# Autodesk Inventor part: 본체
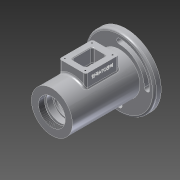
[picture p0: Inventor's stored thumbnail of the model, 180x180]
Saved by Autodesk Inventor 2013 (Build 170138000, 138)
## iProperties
Created: 2017-05
Part Number: 본체
Material: 알루미늄 6061
Document SubType Name: Modeling
Designer: MR
Density: 2.71 g/cm^3
Mass: 688.343 g
Surface Area: 623.745 cm^2
Volume: 254.001 cm^3
Author: MR
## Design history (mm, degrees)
sketch "스케치2"
  geometry: C1 r 31 at (0, 0); 1 further point
  constraints: 1 centre point, 1 coincident
  dimensions: "d0" = 62 diameter of C1
extrude "돌출1" new body sketch "스케치2" distance "d2" = 115; taper "d3" = 0 deg
sketch "스케치3"
  geometry: L1 (-31, -115)-(-31, 0) reference; L2 (-31, 0)-(31, 0) reference; L3 (31, 0)-(31, -115) reference; L4 (31, -115)-(-31, -115) reference; L5 (-31, -115)-(-31, 0) reference; L6 (-31, 0)-(31, 0) reference; L7 (31, 0)-(31, -115) reference; L8 (31, -115)-(-31, -115) reference; L9 (20, 0)-(20, -9); L10 (20, -9)-(24, -9); L11 (24, -9)-(24, -12); L12 (24, -12)-(20, -12); L13 (20, -12)-(20, -21); L14 (20, -21)-(17.5, -21); L15 (17.5, -21)-(17.5, -24.25); L16 (17.5, -24.25)-(18.5, -24.25); L17 (18.5, -24.25)-(18.5, -26); L18 (18.5, -26)-(17.5, -26); L19 (17.5, -26)-(17.5, -37); L20 (17.5, -37)-(26, -37); L21 (26, -37)-(26, -75); L22 (26, -75)-(17.5, -75); L23 (17.5, -75)-(17.5, -86); L24 (17.5, -86)-(16.5, -86); L25 (16.5, -86)-(16.5, -91); L26 (16.5, -91)-(10, -91); L27 (10, -91)-(10, -93.7); L28 (10, -93.7)-(12.5, -93.7); L29 (12.904, -101)-(16, -101); L30 (16, -101)-(19, -115); L31 (0, 0)-(0, -115); L32 (12.5, -93.7)-(12.5, -100.3); L33 (12.5, -100.3)-(12.904, -101); L34 (0, 0)-(20, 0); L35 (0, -115)-(19, -115)
  constraints: 54 end point, 11 parallel, 10 perpendicular, 4 point on line, 2 collinear, 1 midpoint
  dimensions: "d4" = 38 diameter of L30.end L31; "d6" = 32 diameter of L29.end L31; "d9" = 20 diameter of L27 L31; "d11" = 38 distance of L20.end L21.end; "d12" = 3 distance of L10.end L11.end; "d13" = 12 distance from line of L12 L9.start; "d14" = 21 vertical distance of L14.end L9.start; "d15" = 26 vertical distance of L17.end L9.start; "d16" = 11 distance of L18.end L19.end; "d17" = 35 diameter of L19 L31; "d18" = 52 diameter of L21 L31; "d19" = 33 diameter of L25 L31; "d21" = 11 distance of L22.end L23.end; "d23" = 30 deg angle of L32 L33; "d24" = 0.7 distance from line of L32.end L29; "d25" = 7.3 distance between parallel lines of L28 L29; "d26" = 2.7 distance of L26.end L27.end; "d27" = 48 diameter of L11 L31; "d28" = 40 diameter of L13 L31; "d29" = 40 diameter of L9 L31; "d31" = 35 diameter of L15 L31; "d32" = 37 diameter of L17 L31; "d33" = 1.75 distance of L16.end L17.end; "d34" = 14 distance between parallel lines of L29 L4; "d35" = 25 diameter of L32 L31
revolve "회전1" sketch "스케치3" stored, may be unused: angle "d36" = 90 deg
node "작업 평면2"
sketch "스케치5"
  geometry: L1 (0, -41.5)-(0, 41.5); L2 (41.5, 0)-(-41.5, 0); C1 r 53 at (0, 0); C2 r 37.5 at (0, 0); C3 r 31 at (0, 0) reference; A1 r 41.5 centre (0, 0) between (0, 41.5) and (-41.5, 0); A2 r 4 centre (41.5, 0) between (45.5, 0) and (37.5, 0); A3 r 4 centre (0, -41.5) between (0, -37.5) and (0, -45.5); A4 r 4 centre (0, 41.5) between (0, 37.5) and (0, 45.5); A5 r 4 centre (-41.5, 0) between (-45.5, 0) and (-37.5, 0); A6 r 45.5 centre (0, 0) between (0, 45.5) and (-45.5, 0); A7 r 45.5 centre (0, 0) between (0, -45.5) and (45.5, 0); A8 r 37.5 centre (0, 0) between (0, 37.5) and (-37.5, 0); A9 r 37.5 centre (0, 0) between (0, -37.5) and (37.5, 0); 1 further point
  constraints: 20 point on circle, 11 centre point, 10 coincident, 6 point on line, 4 end point, 2 midpoint, 1 perpendicular, 1 tangent, 1 vertical
  dimensions: "d39" = 106 diameter of C1; "d43" = 83 diameter of A1; "d45" = 75 diameter of C2; "d46" = 8 diameter of A2; "d47" = 8 diameter of A3; "d48" = 8 diameter of A4; "d49" = 8 radial gap between concentric circles of C2 A6; "d50" = 8 radial gap between concentric circles of A7 C2; "d53" = 37.5 radius of A8; "d54" = 37.5 radius of A9
node "작업 평면4"
node "작업 평면3"
sketch "스케치7"
  geometry: L1 (-31, 0)-(31, 0) reference; L2 (0, 0)-(0, -56); L3 (20, -31)-(-20, -31); L4 (-20, -31)-(-20, -81); L5 (-20, -81)-(20, -81); L6 (20, -81)-(20, -31); L7 (20, -31)-(-20, -81); L8 (-20, -31)-(20, -81); 1 further point
  constraints: 14 end point, 3 midpoint, 2 parallel, 2 perpendicular, 1 horizontal
  dimensions: "d82" = 56 distance of L2.end L2.start; "d83" = 40 distance of L4.end L5.end; "d84" = 50 distance of L5.end L3.start
extrude "돌출5" join sketch "스케치7" stored distance "d85" = 56 (= d82); taper "d86" = 0 deg
sketch "스케치8"
  geometry: L1 (-20, 31)-(20, 31) reference; L2 (20, 31)-(20, 81) reference; L3 (20, 81)-(-20, 81) reference; L4 (-20, 81)-(-20, 31) reference; L5 (-11, 40)-(11, 40); L6 (11, 40)-(11, 72); L7 (11, 72)-(-11, 72); L8 (-11, 72)-(-11, 40); L9 (-11, 40)-(11, 72); L10 (11, 40)-(-11, 72); L11 (31, 0)-(-31, 0) reference; L12 (20, 81)-(20, 31) reference; L13 (20, 31)-(-20, 31) reference; L14 (-20, 31)-(-20, 81) reference; L15 (-20, 81)-(20, 81) reference; L16 (-20, 31)-(20, 81); 5 further points
  constraints: 14 end point, 4 midpoint, 2 parallel, 1 horizontal, 1 perpendicular
  dimensions: "d87" = 22 distance of L6.end L7.end; "d89" = 32 distance of L5.end L6.end
extrude "돌출6" cut sketch "스케치8" stored distance "d90" = 10; taper "d91" = 0 deg
sketch "스케치9"
  geometry: L1 (-20, 31)-(20, 31) reference; L2 (20, 31)-(20, 81) reference; L3 (20, 81)-(-20, 81) reference; L4 (-20, 81)-(-20, 31) reference; L5 (0, 31)-(0, 81); L6 (-20, 56)-(20, 56); 5 further points
  constraints: 4 end point, 4 midpoint, 2 horizontal alignment, 2 vertical alignment
  dimensions: "d92" = 16 distance from line of point (-16, 35.5) L5; "d94" = 20.5 distance from line of point (-16, 35.5) L6; "d95" = 41 distance of point (-16, 76.5) point (-16, 35.5); "d96" = 31 distance of point (15, 35.5) point (-16, 35.5)
hole "구멍1" sketch "스케치9" at (-16, 35.5), (-16, 76.5), (15, 76.5), (15, 35.5) diameter "d97" = 2.459; stored, may be unused: countersink angle "d101" = 90 deg, drill point angle "d103" = 118 deg; dims "d98" = 6, "d99" = 4, "d100" = 2, "d102" = 8
fillet "모깎기2" dims "d109" = 0.3
fillet "모깎기3" dims "d110" = 3
fillet "모깎기4" dims "d111" = 0.3
extrude "돌출7" join sketch "스케치5" distance "d112" = 10; taper "d113" = 0 deg
fillet "모깎기5" dims "d116" = 3
fillet "모깎기6" dims "d117" = 3
fillet "모깎기7" dims "d118" = 3
fillet "모깎기8" dims "d119" = 3
sketch "스케치10"
  geometry: L1 (0, 0)-(0, 41.5); L2 (0, 0)-(-41.5, 0); L3 (0, 0)-(41.5, 0); L4 (0, 0)-(0, -41.5); C1 r 53 at (0, 0) reference; A1 r 4 centre (-41.5, 0) between (-45.5, 0) and (-37.5, 0); A2 r 4 centre (41.5, 0) between (45.5, 0) and (37.5, 0); A3 r 4 centre (0, -41.5) between (0, -37.5) and (0, -45.5); A4 r 37.5 centre (0, 0) between (0, 37.5) and (-37.5, 0); A5 r 45.5 centre (0, 0) between (0, 45.5) and (-45.5, 0); A6 r 37.5 centre (0, 0) between (0, -37.5) and (37.5, 0); A7 r 45.5 centre (0, 0) between (0, -45.5) and (45.5, 0); A8 r 4 centre (0, 41.5) between (0, 37.5) and (0, 45.5)
  constraints: 16 point on circle, 8 centre point, 8 coincident, 8 end point, 3 point on line, 2 perpendicular, 1 collinear, 1 vertical
  dimensions: "d130" = 41.5 distance of L1.start L1.end; "d132" = 41.5 distance of L1.start L2.end; "d133" = 8 diameter of A1; "d134" = 41.5 distance of L1.start L3.end; "d135" = 8 diameter of A2; "d136" = 41.5 distance of L1.start L4.end; "d137" = 8 diameter of A3; "d140" = 37.5 radius of A6; "d141" = 45.5 radius of A5
extrude "돌출9" cut sketch "스케치10" stored distance "d142" = 10; taper "d143" = 0 deg
node "작업 평면5"
sketch "스케치11"
  geometry: L1 (-31, 0)-(31, 0) reference; L2 (44, -34)-(44, -78) reference; 2 further points
  constraints: 1 other
  dimensions: "d145" = 56 distance from line of point (36, -56) L1; "d146" = 8 distance from line of point (36, -56) L2
feature "엠보싱1" sketch "스케치11" dims "d4" = 38, "d6" = 32, "d9" = 20, "d11" = 38, "d12" = 3, "d13" = 12, "d14" = 21, "d15" = 26, "d16" = 11, "d17" = 35, "d18" = 52, "d19" = 33, "d21" = 11, "d23" = 30 deg, "d24" = 0.7, "d25" = 7.3, "d26" = 2.7, "d27" = 48, "d28" = 40, "d29" = 40, "d31" = 35, "d32" = 37, "d33" = 1.75, "d34" = 14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
hole "구멍2" diameter "d151" = 40.376; stored, may be unused: countersink angle "d155" = 90 deg, drill point angle "d157" = 0 deg; dims "d149" = 10, "d150" = 10, "d152" = 9, "d153" = 4, "d154" = 2, "d156" = 9
fillet "모깎기9" dims "d158" = 3
chamfer "모따기1" distance "d159" = 1; stored, may be unused: second distance "d160" = 2, angle "d161" = 45 deg
node "솔리드1"
node "투영된 루프1"
node "절단 모서리 투영1"
node "절단 모서리 투영2"
other parameters: "d38" = -3, "d44" = 91, "d81" = 44, "d104" = 0.5, "d105" = 2, "d106" = 0
